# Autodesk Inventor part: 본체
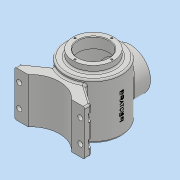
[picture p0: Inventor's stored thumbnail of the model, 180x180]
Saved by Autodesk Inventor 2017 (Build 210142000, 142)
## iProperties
Part Number: 본체
Material: 일반
Document SubType Name: Modeling
Designer: MRC
Density: 1 g/cm^3
Appearance: 기본값
Author: MRC
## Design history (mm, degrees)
sketch "스케치1"
  geometry: L1 (0, 62)-(0, -58); L2 (43, -41.887)-(43, 43); L3 (43, 43)-(27, 43); L4 (27, 43)-(27, 62); L5 (27, 62)-(36, 62); L6 (36, 62)-(36, 50); L7 (36, 50)-(50, 50); L8 (50, 50)-(50, -46.336); A1 r 106 centre (0, 55) between (0, -51) and (43, -41.887); A2 r 113 centre (0, 55) between (0, -58) and (50, -46.336); 1 further point
  constraints: 16 end point, 6 perpendicular, 4 point on circle, 3 point on line, 2 centre point, 2 vertical, 1 coincident, 1 horizontal alignment
  dimensions: "d0" = 120 distance of L1.start L1.end; "d1" = 62 distance of point (0, 0) L1.start; "d2" = 100 diameter of L8 L1; "d3" = 72 diameter of L6 L1; "d4" = 54 diameter of L4 L1; "d5" = 113 radius of A2; "d6" = 7 radial gap between concentric circles of A2 A1; "d7" = 86 diameter of L2 L1; "d8" = 19 distance of L3.end L4.end; "d9" = 108 distance from line of L7 L1.end
revolve "회전1" sketch "스케치1" stored, may be unused: angle "d10" = 90 deg
node "작업 평면1"
sketch "스케치2"
  geometry: C1 r 36 at (0, 0); 1 further point
  constraints: 1 centre point, 1 coincident
  dimensions: "d12" = 72 diameter of C1
extrude "돌출1" join sketch "스케치2" stored distance "d13" = 10; taper "d14" = 0 deg
sketch "스케치3"
  geometry: C1 r 27 at (0, 0); 1 further point
  constraints: 1 centre point, 1 coincident
  dimensions: "d15" = 54 diameter of C1
extrude "돌출2" cut sketch "스케치3" stored distance "d16" = 10; taper "d17" = 0 deg
sketch "스케치4"
  geometry: 2 further points
  constraints: 1 vertical alignment
  dimensions: "d18" = 32.5 distance of point (0, 0) point (0, 32.5)
hole "구멍1" sketch "스케치4" at (0, 32.5) diameter "d19" = 3.242; stored, may be unused: countersink angle "d23" = 90 deg, drill point angle "d25" = 118 deg; dims "d20" = 8, "d21" = 4, "d22" = 2, "d24" = 10
sketch "스케치5"
  geometry: 2 further points
  constraints: 1 vertical alignment
  dimensions: "d29" = 32.5 distance of point (0, 0) point (0, 32.5)
hole "구멍2" sketch "스케치5" at (0, 32.5) diameter "d30" = 3.242; stored, may be unused: countersink angle "d34" = 90 deg, drill point angle "d36" = 118 deg; dims "d31" = 8, "d32" = 4, "d33" = 2, "d35" = 10
node "작업 평면2"
sketch "스케치6"
  geometry: L1 (-26.694, -42.278)-(-62, -67); L2 (-62, -67)-(-62, -77); L3 (-62, -77)-(-38.5, -77); L4 (26.694, -42.278)-(62, -67); L5 (62, -67)-(62, -77); L6 (62, -77)-(38.5, -77); A1 r 50 centre (0, 0) between (-26.694, -42.278) and (26.694, -42.278) reference; A2 r 52.096 centre (0, -112.096) between (38.5, -77) and (-38.5, -77); 1 further point
  constraints: 12 end point, 4 point on circle, 2 equal length, 2 perpendicular, 2 vertical, 1 centre point, 1 collinear, 1 vertical alignment
  dimensions: "d41" = 77 distance of L6.end L3.end; "d42" = 124 distance between parallel lines of L2 L5; "d43" = 77 distance from line of L6 point (0, 0); "d44" = 17 distance edge to line of A2 L6; "d45" = 10 distance of L4.end L5.end; "d46" = 55 deg angle of L4 L5; "d47" = 55 deg angle of L2 L1
extrude "돌출3" join sketch "스케치6" stored distance "d48" = 80; taper "d49" = 0 deg
sketch "스케치7"
  geometry: L1 (23.5, -80)-(0, -80) reference; C1 r 4.5 at (8, -60); 1 further point
  constraints: 1 centre point
  dimensions: "d50" = 9 diameter of C1; "d51" = 54 horizontal distance of C1.centre point (62, -42); "d52" = 20 distance from line of L1 C1.centre
extrude "돌출4" cut sketch "스케치7" distance "d53" = 6; taper "d54" = 0 deg
sketch "스케치8"
  geometry: L1 (0, 7)-(-8, 7); L2 (-8, 7)-(-8, -7); L3 (-8, -7)-(0, -7); L4 (-8, -20)-(-8, 60) reference; C1 r 4.5 at (0, 0) reference; A1 r 7 centre (0, 0) between (0, -7) and (0, 7); 1 further point
  constraints: 6 end point, 2 perpendicular, 2 point on circle, 2 tangent, 1 centre point, 1 collinear, 1 concentric, 1 horizontal
  dimensions: "d55" = 14 diameter of A1
extrude "돌출5" cut sketch "스케치8" stored distance "d56" = 6; taper "d57" = 0 deg
node "작업 평면3"
sketch "스케치9"
  geometry: 2 further points
  constraints: 1 coincident, 1 other
feature "엠보싱1" sketch "스케치9" dims "d58" = 0.5, "d59" = 0
chamfer "모따기1" distance "d60" = 1; stored, may be unused: second distance "d61" = 2, angle "d62" = 45 deg
fillet "모깎기1" dims "d63" = 3
fillet "모깎기2" dims "d64" = 3
fillet "모깎기6" dims "d68" = 3
node "솔리드1"
pattern_circular "원형 패턴1" dims angle "d27" = 360 deg
pattern_circular "원형 패턴2" dims angle "d38" = 360 deg
mirror "미러1"
mirror "미러2"
other parameters: "d11" = 65
